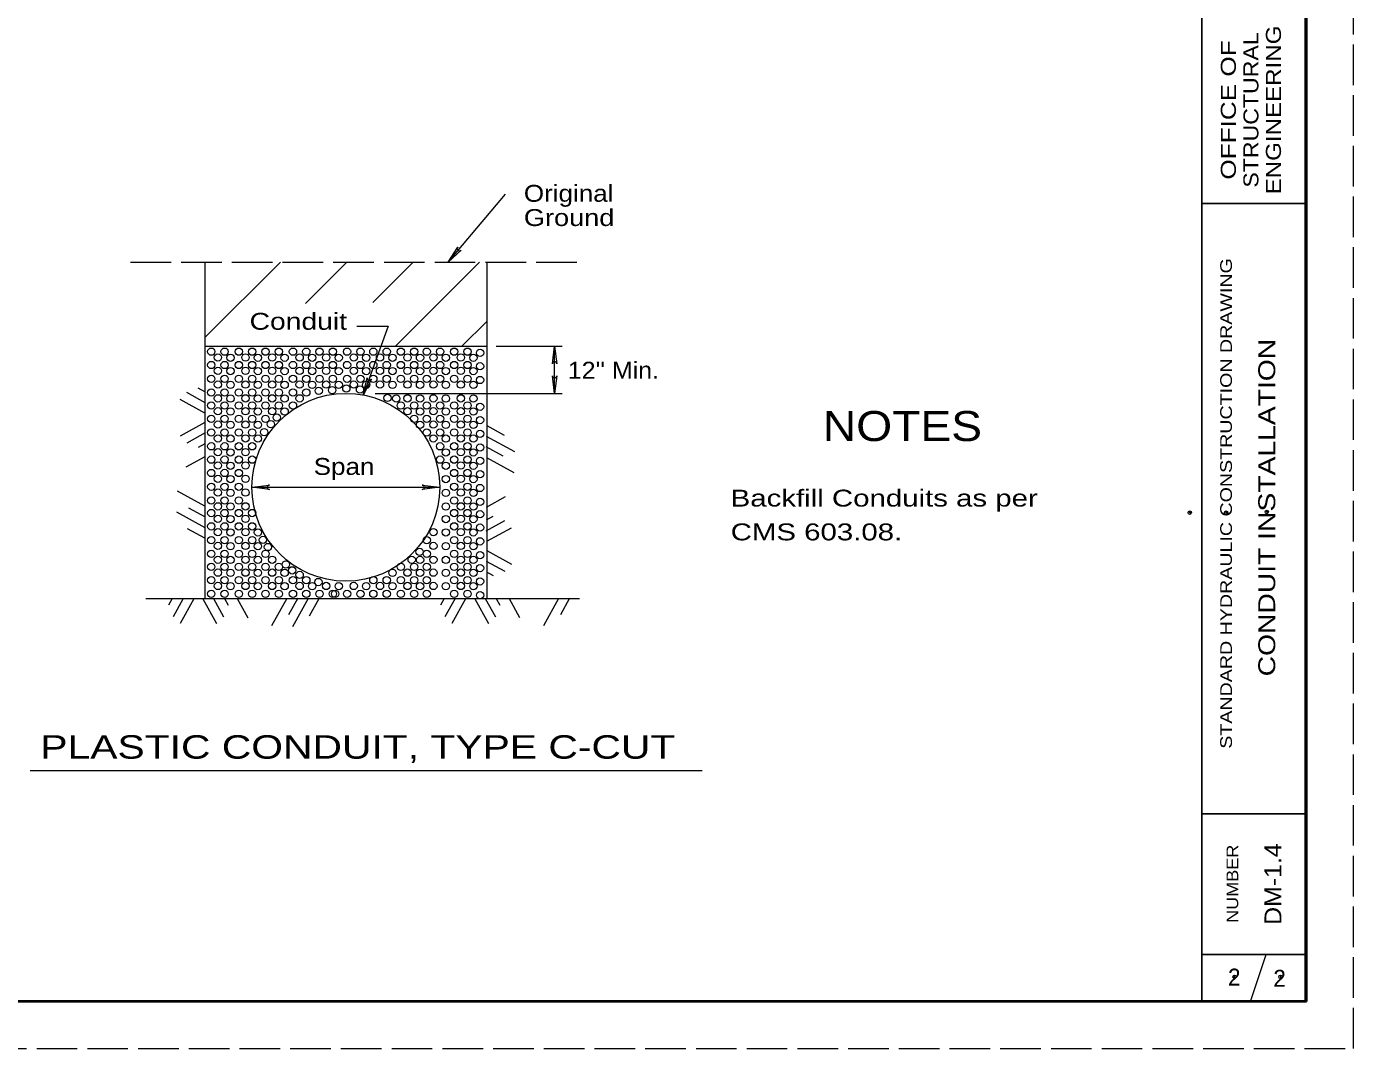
# Model space of a CAD drawing. Extents: x 750.7 to 784.7, y 834.8 to 878.8.
# Drawn here: x 770.52 to 784.65, y 834.78 to 845.67 of the extents above; entities that cross this region are included whole.
import ezdxf
from ezdxf.enums import TextEntityAlignment as Align

# ---------------------------------------------------------------- set-up
doc = ezdxf.new("R2010")
doc.units = 0
doc.header["$LTSCALE"] = 0.072
doc.header["$PDMODE"] = 32
doc.header["$PDSIZE"] = 0.036
doc.linetypes.add('LONG_DASHED', pattern=[7.5, 6, -1.5])
doc.layers.add('1', color=7, linetype='Continuous', lineweight=13)
doc.layers.add('47', color=7, linetype='Continuous', lineweight=13)

msp = doc.modelspace()

# ---------------------------------------------------------------- linework, layer by layer
at = {"layer": '1', "lineweight": 25}
for p, q in [((783.03717, 835.28433), (783.03717, 856.28433)), ((784.13717, 856.28433), (784.13717, 835.28433)), ((784.13717, 843.78433), (783.03717, 843.78433)), ((784.13717, 837.28433), (783.03717, 837.28433)), ((784.13717, 835.78433), (783.03717, 835.78433)), ((784.15083, 835.28433), (752.65083, 835.28433))]:
    msp.add_line(p, q, dxfattribs=at)
at = {"layer": '1', "lineweight": 40}
msp.add_line((784.147, 856.28433), (784.147, 835.28433), dxfattribs=at)
at = {"layer": '1'}
for p, q in [((775.01125, 843.15875), (775.62233, 843.88067)), ((772.42208, 843.15875), (772.42208, 839.5755)), ((772.42208, 842.35508), (773.22567, 843.15875)), ((773.4925, 842.71842), (773.93275, 843.15875)), ((774.21, 842.72883), (774.63983, 843.15875)), ((774.45017, 842.26192), (775.34692, 843.15875)), ((775.42208, 843.15875), (775.42208, 839.5755)), ((775.15717, 842.26192), (775.42208, 842.52683)), ((772.42208, 842.26192), (775.42208, 842.26192)), ((775.52308, 842.26192), (776.22442, 842.26192)), ((776.1445, 841.76058), (776.1445, 842.26192)), ((772.4235, 841.66092), (772.228, 841.76875)), ((772.42208, 841.7775), (772.35075, 841.81683)), ((774.236, 841.76058), (776.22442, 841.76058)), ((772.41958, 841.54883), (772.157, 841.69375)), ((772.41958, 841.45092), (772.157, 841.306)), ((772.4235, 841.33883), (772.228, 841.231)), ((775.42208, 841.41875), (775.6065, 841.317)), ((772.42208, 841.22225), (772.35075, 841.18292)), ((775.41425, 841.19467), (775.59267, 841.09625)), ((775.41817, 841.30667), (775.71933, 841.1405)), ((772.42258, 841.08592), (772.2185, 840.97333)), ((775.41958, 841.0775), (775.71058, 840.91692)), ((772.42208, 840.55875), (772.13108, 840.71933)), ((772.92208, 840.76083), (774.92208, 840.76083)), ((775.41908, 840.55033), (775.62317, 840.66292)), ((772.4235, 840.32958), (772.12233, 840.49575)), ((772.42742, 840.44158), (772.249, 840.54)), ((775.41817, 840.29742), (775.61367, 840.40525)), ((775.41958, 840.414), (775.49092, 840.45333)), ((772.41958, 840.2175), (772.23517, 840.31925)), ((775.42208, 840.18533), (775.68467, 840.33025)), ((775.42208, 840.08742), (775.68467, 839.9425)), ((775.41817, 839.97533), (775.61367, 839.8675)), ((775.41958, 839.85875), (775.49092, 839.81942)), ((771.79442, 839.5755), (776.40983, 839.5755)), ((772.0745, 839.5755), (772.03517, 839.50417)), ((772.19108, 839.57692), (772.08325, 839.38142)), ((772.30317, 839.573), (772.15825, 839.31042)), ((772.40108, 839.573), (772.546, 839.31042)), ((772.51317, 839.57692), (772.621, 839.38142)), ((772.62975, 839.5755), (772.66908, 839.50417)), ((772.76608, 839.576), (772.87867, 839.37192)), ((773.29325, 839.5755), (773.13267, 839.2845)), ((773.41042, 839.58083), (773.312, 839.40242)), ((773.52242, 839.57692), (773.35625, 839.27575)), ((773.6345, 839.573), (773.53275, 839.38858)), ((774.96892, 839.57617), (774.92958, 839.50483)), ((775.0855, 839.57758), (774.97767, 839.38208)), ((775.19758, 839.57367), (775.05267, 839.31108)), ((775.2955, 839.57367), (775.44042, 839.31108)), ((775.40758, 839.57758), (775.51542, 839.38208)), ((775.52417, 839.57617), (775.5635, 839.50483)), ((775.6605, 839.57667), (775.77308, 839.37258)), ((776.18767, 839.57617), (776.02708, 839.28517)), ((776.30483, 839.5815), (776.20642, 839.40308)), ((770.56125, 837.74617), (777.71625, 837.74617)), ((783.55383, 835.28433), (783.7205, 835.78433))]:
    msp.add_line(p, q, dxfattribs=at)
at = {"layer": '1', "linetype": 'LONG_DASHED'}
msp.add_line((771.62908, 843.15875), (776.42258, 843.15875), dxfattribs=at)
msp.add_lwpolyline([(750.65083, 834.78433), (784.65083, 834.78433), (784.65083, 856.78433), (750.65083, 856.78433)], close=True, dxfattribs=at)
at = {"layer": '1', "lineweight": 40}
for points in [[(784.15083, 835.28433), (752.65083, 835.28433), (752.65083, 856.28433), (784.15083, 856.28433)], [(784.15083, 835.28433), (752.65083, 835.28433), (752.65083, 856.28433)]]:
    msp.add_lwpolyline(points, dxfattribs=at)
at = {"layer": '1'}
msp.add_lwpolyline([(774.0385, 842.47633), (774.37317, 842.47633), (774.10817, 841.74333)], dxfattribs=at)
for centre, radius in [((772.48963, 842.20494), 0.03892), ((772.56066, 842.14281), 0.03892), ((772.63166, 842.20497), 0.03892), ((772.69383, 842.14047), 0.03892), ((772.78255, 842.20494), 0.03892), ((772.85358, 842.14281), 0.03892), ((772.92458, 842.20497), 0.03892), ((772.98674, 842.14047), 0.03892), ((773.06663, 842.20494), 0.03892), ((773.13766, 842.14281), 0.03892), ((773.20866, 842.20497), 0.03892), ((773.27083, 842.14047), 0.03892), ((773.35955, 842.20494), 0.03892), ((773.43058, 842.14281), 0.03892), ((773.50158, 842.20497), 0.03892), ((773.56374, 842.14047), 0.03892), ((773.64263, 842.20494), 0.03892), ((773.71366, 842.14281), 0.03892), ((773.78466, 842.20497), 0.03892), ((773.84683, 842.14047), 0.03892), ((773.93555, 842.20494), 0.03892), ((774.00658, 842.14281), 0.03892), ((774.07758, 842.20497), 0.03892), ((774.13974, 842.14047), 0.03892), ((774.21521, 842.20494), 0.03892), ((774.28624, 842.14281), 0.03892), ((774.35724, 842.20497), 0.03892), ((774.41941, 842.14047), 0.03892), ((774.50813, 842.20494), 0.03892), ((774.57916, 842.14281), 0.03892), ((774.65016, 842.20497), 0.03892), ((774.71233, 842.14047), 0.03892), ((774.78338, 842.20494), 0.03892), ((774.85441, 842.14281), 0.03892), ((774.92541, 842.20497), 0.03892), ((774.98758, 842.14047), 0.03892), ((775.0763, 842.20494), 0.03892), ((775.14733, 842.14281), 0.03892), ((775.21833, 842.20497), 0.03892), ((775.28049, 842.14047), 0.03892), ((775.35149, 842.19164), 0.03892), ((772.48963, 842.06286), 0.03892), ((772.56066, 842.00072), 0.03892), ((772.63166, 842.06289), 0.03892), ((772.69383, 841.99839), 0.03892), ((772.78255, 842.06286), 0.03892), ((772.85358, 842.00072), 0.03892), ((772.92458, 842.06289), 0.03892), ((772.98674, 841.99839), 0.03892), ((773.06663, 842.06286), 0.03892), ((773.13766, 842.00072), 0.03892), ((773.20866, 842.06289), 0.03892), ((773.27083, 841.99839), 0.03892), ((773.35955, 842.06286), 0.03892), ((773.43058, 842.00072), 0.03892), ((773.50158, 842.06289), 0.03892), ((773.56374, 841.99839), 0.03892), ((773.64263, 842.06286), 0.03892), ((773.71366, 842.00072), 0.03892), ((773.78466, 842.06289), 0.03892), ((773.84683, 841.99839), 0.03892), ((773.93555, 842.06286), 0.03892), ((774.00658, 842.00072), 0.03892), ((774.07758, 842.06289), 0.03892), ((774.13974, 841.99839), 0.03892), ((774.21521, 842.06286), 0.03892), ((774.28624, 842.00072), 0.03892), ((774.35724, 842.06289), 0.03892), ((774.41941, 841.99839), 0.03892), ((774.50813, 842.06286), 0.03892), ((774.57916, 842.00072), 0.03892), ((774.65016, 842.06289), 0.03892), ((774.71233, 841.99839), 0.03892), ((774.78338, 842.06286), 0.03892), ((774.85441, 842.00072), 0.03892), ((774.92541, 842.06289), 0.03892), ((774.98758, 841.99839), 0.03892), ((775.0763, 842.06286), 0.03892), ((775.14733, 842.00072), 0.03892), ((775.21833, 842.06289), 0.03892), ((775.28049, 841.99839), 0.03892), ((775.35149, 842.04956), 0.03892), ((772.48963, 841.91636), 0.03892), ((772.63166, 841.91639), 0.03892), ((772.78255, 841.91636), 0.03892), ((772.92458, 841.91639), 0.03892), ((773.06663, 841.91636), 0.03892), ((773.20866, 841.91639), 0.03892), ((773.35955, 841.91636), 0.03892), ((773.50158, 841.91639), 0.03892), ((773.64263, 841.91636), 0.03892), ((773.78466, 841.91639), 0.03892), ((773.93555, 841.91636), 0.03892), ((774.07758, 841.91639), 0.03892), ((774.21521, 841.91636), 0.03892), ((774.35724, 841.91639), 0.03892), ((774.50813, 841.91636), 0.03892), ((774.65016, 841.91639), 0.03892), ((774.78338, 841.91636), 0.03892), ((774.92541, 841.91639), 0.03892), ((775.0763, 841.91636), 0.03892), ((775.21833, 841.91639), 0.03892), ((775.35149, 841.90306), 0.03892), ((772.48963, 841.76978), 0.03892), ((772.56066, 841.85422), 0.03892), ((772.63166, 841.76981), 0.03892), ((772.69383, 841.85189), 0.03892), ((772.78255, 841.76978), 0.03892), ((772.85358, 841.85422), 0.03892), ((772.92458, 841.76981), 0.03892), ((773.92208, 840.76083), 1), ((772.98674, 841.85189), 0.03892), ((773.06663, 841.76978), 0.03892), ((773.13766, 841.85422), 0.03892), ((773.20866, 841.76981), 0.03892), ((773.27083, 841.85189), 0.03892), ((773.35955, 841.76978), 0.03892), ((773.43058, 841.85422), 0.03892), ((773.50158, 841.76981), 0.03892), ((773.56374, 841.85189), 0.03892), ((773.63373, 841.78758), 0.03892), ((773.71366, 841.85422), 0.03892), ((773.77683, 841.79412), 0.03892), ((773.84683, 841.85189), 0.03892), ((773.92767, 841.81187), 0.03892), ((774.00658, 841.85422), 0.03892), ((774.07315, 841.80086), 0.03892), ((774.13974, 841.85189), 0.03892), ((774.28624, 841.85422), 0.03892), ((774.41941, 841.85189), 0.03892), ((774.57916, 841.85422), 0.03892), ((774.71233, 841.85189), 0.03892), ((774.85441, 841.85422), 0.03892), ((774.98758, 841.85189), 0.03892), ((775.14733, 841.85422), 0.03892), ((775.28049, 841.85189), 0.03892), ((772.48963, 841.63211), 0.03892), ((772.56066, 841.70764), 0.03892), ((772.63166, 841.63214), 0.03892), ((772.69383, 841.70531), 0.03892), ((772.78255, 841.63211), 0.03892), ((772.85358, 841.70764), 0.03892), ((772.92458, 841.63214), 0.03892), ((772.98674, 841.70531), 0.03892), ((773.06663, 841.63211), 0.03892), ((773.13766, 841.70764), 0.03892), ((773.20866, 841.63214), 0.03892), ((773.27083, 841.70531), 0.03892), ((773.35955, 841.63211), 0.03892), ((773.43058, 841.70764), 0.03892), ((774.36614, 841.71203), 0.03892), ((774.45934, 841.70528), 0.03892), ((774.50813, 841.63211), 0.03892), ((774.57916, 841.70764), 0.03892), ((774.65016, 841.63214), 0.03892), ((774.71233, 841.70531), 0.03892), ((774.78338, 841.63211), 0.03892), ((774.85441, 841.70764), 0.03892), ((774.92541, 841.63214), 0.03892), ((774.98758, 841.70531), 0.03892), ((775.0763, 841.63211), 0.03892), ((775.14733, 841.70764), 0.03892), ((775.21833, 841.63214), 0.03892), ((775.28049, 841.70531), 0.03892), ((775.35149, 841.61881), 0.03892), ((772.48963, 841.49003), 0.03892), ((772.56066, 841.56997), 0.03892), ((772.63166, 841.49006), 0.03892), ((772.69383, 841.56764), 0.03892), ((772.78255, 841.49003), 0.03892), ((772.85358, 841.56997), 0.03892), ((772.92458, 841.49006), 0.03892), ((772.98674, 841.56764), 0.03892), ((773.06663, 841.49003), 0.03892), ((773.12433, 841.43236), 0.03892), ((773.13766, 841.56997), 0.03892), ((773.18642, 841.50338), 0.03892), ((773.27083, 841.56764), 0.03892), ((774.57916, 841.56997), 0.03892), ((774.65016, 841.49006), 0.03892), ((774.71233, 841.56764), 0.03892), ((774.78338, 841.49003), 0.03892), ((774.85441, 841.56997), 0.03892), ((774.92541, 841.49006), 0.03892), ((774.98758, 841.56764), 0.03892), ((775.0763, 841.49003), 0.03892), ((775.14733, 841.56997), 0.03892), ((775.21833, 841.49006), 0.03892), ((775.28049, 841.56764), 0.03892), ((775.35149, 841.47672), 0.03892), ((772.48963, 841.34353), 0.03892), ((772.56066, 841.42789), 0.03892), ((772.63166, 841.34356), 0.03892), ((772.69383, 841.42556), 0.03892), ((772.78255, 841.34353), 0.03892), ((772.85358, 841.42789), 0.03892), ((772.92458, 841.34356), 0.03892), ((772.98674, 841.42556), 0.03892), ((773.05334, 841.34794), 0.03892), ((774.71233, 841.42556), 0.03892), ((774.78338, 841.34353), 0.03892), ((774.85441, 841.42789), 0.03892), ((774.92541, 841.34356), 0.03892), ((774.98758, 841.42556), 0.03892), ((775.0763, 841.34353), 0.03892), ((775.14733, 841.42789), 0.03892), ((775.21833, 841.34356), 0.03892), ((775.28049, 841.42556), 0.03892), ((775.35149, 841.33022), 0.03892), ((772.48963, 841.19694), 0.03892), ((772.56066, 841.28139), 0.03892), ((772.63166, 841.19697), 0.03892), ((772.69383, 841.27906), 0.03892), ((772.78255, 841.19694), 0.03892), ((772.85358, 841.28139), 0.03892), ((772.92458, 841.19697), 0.03892), ((772.98674, 841.27906), 0.03892), ((774.85441, 841.28139), 0.03892), ((774.92541, 841.19697), 0.03892), ((774.98758, 841.27906), 0.03892), ((775.0763, 841.19694), 0.03892), ((775.14733, 841.28139), 0.03892), ((775.21833, 841.19697), 0.03892), ((775.28049, 841.27906), 0.03892), ((775.35149, 841.18364), 0.03892), ((772.48963, 841.05494), 0.03892), ((772.56066, 841.13481), 0.03892), ((772.63166, 841.05497), 0.03892), ((772.69383, 841.13247), 0.03892), ((772.78255, 841.05494), 0.03892), ((772.85358, 841.13481), 0.03892), ((772.92458, 841.05497), 0.03892), ((774.92541, 841.05497), 0.03892), ((774.98758, 841.13247), 0.03892), ((775.0763, 841.05494), 0.03892), ((775.14733, 841.13481), 0.03892), ((775.21833, 841.05497), 0.03892), ((775.28049, 841.13247), 0.03892), ((775.35149, 841.04164), 0.03892), ((772.48963, 840.91286), 0.03892), ((772.56066, 840.99281), 0.03892), ((772.63166, 840.91289), 0.03892), ((772.69383, 840.99047), 0.03892), ((772.78255, 840.91286), 0.03892), ((772.85358, 840.99281), 0.03892), ((774.98758, 840.99047), 0.03892), ((775.0763, 840.91286), 0.03892), ((775.14733, 840.99281), 0.03892), ((775.21833, 840.91289), 0.03892), ((775.28049, 840.99047), 0.03892), ((775.35149, 840.89956), 0.03892), ((772.48963, 840.76636), 0.03892), ((772.56066, 840.85072), 0.03892), ((772.63166, 840.76639), 0.03892), ((772.69383, 840.84839), 0.03892), ((772.78255, 840.76636), 0.03892), ((772.85358, 840.85072), 0.03892), ((774.98758, 840.84839), 0.03892), ((775.0763, 840.76636), 0.03892), ((775.14733, 840.85072), 0.03892), ((775.21833, 840.76639), 0.03892), ((775.28049, 840.84839), 0.03892), ((775.35149, 840.75306), 0.03892), ((772.48963, 840.61978), 0.03892), ((772.56066, 840.70422), 0.03892), ((772.63166, 840.61981), 0.03892), ((772.69383, 840.70189), 0.03892), ((772.78255, 840.61978), 0.03892), ((772.85358, 840.70422), 0.03892), ((774.98758, 840.70189), 0.03892), ((775.0763, 840.61978), 0.03892), ((775.14733, 840.70422), 0.03892), ((775.21833, 840.61981), 0.03892), ((775.28049, 840.70189), 0.03892), ((775.35149, 840.60647), 0.03892), ((772.48963, 840.48661), 0.03892), ((772.56066, 840.55764), 0.03892), ((772.63166, 840.48664), 0.03892), ((772.69383, 840.55531), 0.03892), ((772.78255, 840.48661), 0.03892), ((772.85358, 840.55764), 0.03892), ((772.92458, 840.48664), 0.03892), ((774.98758, 840.55531), 0.03892), ((775.0763, 840.48661), 0.03892), ((775.14733, 840.55764), 0.03892), ((775.21833, 840.48664), 0.03892), ((775.28049, 840.55531), 0.03892), ((775.35149, 840.47331), 0.03892), ((772.48963, 840.34453), 0.03892), ((772.56066, 840.42447), 0.03892), ((772.63166, 840.34456), 0.03892), ((772.69383, 840.42214), 0.03892), ((772.78255, 840.34453), 0.03892), ((772.85358, 840.42447), 0.03892), ((772.92458, 840.34456), 0.03892), ((774.98758, 840.42214), 0.03892), ((775.0763, 840.34453), 0.03892), ((775.14733, 840.42447), 0.03892), ((775.21833, 840.34456), 0.03892), ((775.28049, 840.42214), 0.03892), ((775.35149, 840.33122), 0.03892), ((772.48963, 840.19803), 0.03892), ((772.56066, 840.28239), 0.03892), ((772.63166, 840.19806), 0.03892), ((772.69383, 840.28006), 0.03892), ((772.78255, 840.19803), 0.03892), ((772.85358, 840.28239), 0.03892), ((772.92458, 840.19806), 0.03892), ((772.98674, 840.28006), 0.03892), ((773.04, 840.20012), 0.03892), ((774.78338, 840.19803), 0.03892), ((774.85441, 840.28239), 0.03892), ((774.98758, 840.28006), 0.03892), ((775.0763, 840.19803), 0.03892), ((775.14733, 840.28239), 0.03892), ((775.21833, 840.19806), 0.03892), ((775.28049, 840.28006), 0.03892), ((775.35149, 840.18472), 0.03892), ((772.48963, 840.05144), 0.03892), ((772.56066, 840.13589), 0.03892), ((772.63166, 840.05147), 0.03892), ((772.69383, 840.13356), 0.03892), ((772.78255, 840.05144), 0.03892), ((772.85358, 840.13589), 0.03892), ((772.92458, 840.05147), 0.03892), ((772.98674, 840.13356), 0.03892), ((773.06663, 840.05144), 0.03892), ((773.09325, 840.12462), 0.03892), ((774.70785, 840.07367), 0.03892), ((774.78338, 840.05144), 0.03892), ((774.85441, 840.13589), 0.03892), ((774.98758, 840.13356), 0.03892), ((775.0763, 840.05144), 0.03892), ((775.14733, 840.13589), 0.03892), ((775.21833, 840.05147), 0.03892), ((775.28049, 840.13356), 0.03892), ((775.35149, 840.03814), 0.03892), ((772.48963, 839.91378), 0.03892), ((772.56066, 839.98931), 0.03892), ((772.63166, 839.91381), 0.03892), ((772.69383, 839.98697), 0.03892), ((772.78255, 839.91378), 0.03892), ((772.85358, 839.98931), 0.03892), ((772.92458, 839.91381), 0.03892), ((772.98674, 839.98697), 0.03892), ((773.06663, 839.91378), 0.03892), ((773.13766, 839.98931), 0.03892), ((773.20866, 839.91381), 0.03892), ((773.28408, 839.93821), 0.03892), ((774.50813, 839.91378), 0.03892), ((774.62351, 839.98926), 0.03892), ((774.65016, 839.91381), 0.03892), ((774.71233, 839.98697), 0.03892), ((774.78338, 839.91378), 0.03892), ((774.85441, 839.98931), 0.03892), ((774.98758, 839.98697), 0.03892), ((775.0763, 839.91378), 0.03892), ((775.14733, 839.98931), 0.03892), ((775.21833, 839.91381), 0.03892), ((775.28049, 839.98697), 0.03892), ((775.35149, 839.90047), 0.03892), ((772.48963, 839.77169), 0.03892), ((772.56066, 839.85164), 0.03892), ((772.63166, 839.77172), 0.03892), ((772.69383, 839.84931), 0.03892), ((772.78255, 839.77169), 0.03892), ((772.85358, 839.85164), 0.03892), ((772.92458, 839.77172), 0.03892), ((772.98674, 839.84931), 0.03892), ((773.06663, 839.77169), 0.03892), ((773.13766, 839.85164), 0.03892), ((773.20866, 839.77172), 0.03892), ((773.27083, 839.84931), 0.03892), ((773.35067, 839.87604), 0.03892), ((773.35955, 839.77169), 0.03892), ((773.43058, 839.82712), 0.03892), ((773.50158, 839.77172), 0.03892), ((773.63033, 839.75171), 0.03892), ((774.21521, 839.77169), 0.03892), ((774.35724, 839.77172), 0.03892), ((774.41941, 839.84931), 0.03892), ((774.50813, 839.77169), 0.03892), ((774.57916, 839.85164), 0.03892), ((774.65016, 839.77172), 0.03892), ((774.71233, 839.84931), 0.03892), ((774.78338, 839.77169), 0.03892), ((774.85441, 839.85164), 0.03892), ((774.98758, 839.84931), 0.03892), ((775.0763, 839.77169), 0.03892), ((775.14733, 839.85164), 0.03892), ((775.21833, 839.77172), 0.03892), ((775.28049, 839.84931), 0.03892), ((775.35149, 839.75839), 0.03892), ((772.48963, 839.62519), 0.03892), ((772.56066, 839.70956), 0.03892), ((772.63166, 839.62522), 0.03892), ((772.69383, 839.70722), 0.03892), ((772.78255, 839.62519), 0.03892), ((772.85358, 839.70956), 0.03892), ((772.92458, 839.62522), 0.03892), ((772.98674, 839.70722), 0.03892), ((773.06663, 839.62519), 0.03892), ((773.13766, 839.70956), 0.03892), ((773.20866, 839.62522), 0.03892), ((773.27083, 839.70722), 0.03892), ((773.35955, 839.62519), 0.03892), ((773.43058, 839.70956), 0.03892), ((773.50158, 839.62522), 0.03892), ((773.56374, 839.70722), 0.03892), ((773.64263, 839.62519), 0.03892), ((773.71366, 839.70956), 0.03892), ((773.78466, 839.62522), 0.03892), ((773.80813, 839.62519), 0.03892), ((773.84683, 839.70722), 0.03892), ((773.93555, 839.62519), 0.03892), ((774.00658, 839.70956), 0.03892), ((774.07758, 839.62522), 0.03892), ((774.13974, 839.70722), 0.03892), ((774.21521, 839.62519), 0.03892), ((774.28624, 839.70956), 0.03892), ((774.35724, 839.62522), 0.03892), ((774.41941, 839.70722), 0.03892), ((774.50813, 839.62519), 0.03892), ((774.57916, 839.70956), 0.03892), ((774.65016, 839.62522), 0.03892), ((774.71233, 839.70722), 0.03892), ((774.78338, 839.62519), 0.03892), ((774.85441, 839.70956), 0.03892), ((774.98758, 839.70722), 0.03892), ((775.0763, 839.62519), 0.03892), ((775.14733, 839.70956), 0.03892), ((775.21833, 839.62522), 0.03892), ((775.28049, 839.70722), 0.03892), ((775.35149, 839.61189), 0.03892)]:
    msp.add_circle(centre, radius, dxfattribs=at)
for p in [(782.90825, 840.49033), (783.29458, 840.49033), (783.72742, 840.49767), (783.38525, 835.54808), (783.87367, 835.54708)]:
    msp.add_point(p, dxfattribs=at)
at = {"layer": '47'}
for points in [[(775.15025, 843.28675), (775.01125, 843.15875), (775.1145, 843.317)], [(776.12108, 842.07442), (776.1445, 842.26192), (776.16792, 842.07442)], [(774.19392, 841.91167), (774.10817, 841.74333), (774.14992, 841.92767)], [(776.16792, 841.94808), (776.1445, 841.76058), (776.12108, 841.94808)], [(773.10958, 840.73742), (772.92208, 840.76083), (773.10958, 840.78425)], [(774.73458, 840.78425), (774.92208, 840.76083), (774.73458, 840.73742)]]:
    msp.add_lwpolyline(points, dxfattribs=at)
for centre, start, end in [((775.13239, 843.30187), 139.75297, 319.75297), ((776.14451, 842.07441), 0, 180), ((774.17191, 841.91967), 160.12536, 340.12536), ((776.14449, 841.94809), 180, 0), ((773.10959, 840.76084), 90, 270), ((774.73458, 840.76083), 270, 90)]:
    msp.add_arc(centre, 0.02342, start, end, dxfattribs=at)

# ---------------------------------------------------------------- texts
at = {"layer": '1'}
for s, height, width, p in [('STRUCTURAL', 0.16, 1.15, (783.63892, 844.77871)), ('ENGINEERING', 0.16, 1.2, (783.87892, 844.77879)), ('OFFICE OF', 0.16, 1.3, (783.39892, 844.77871)), ('STANDARD HYDRAULIC CONSTRUCTION DRAWING', 0.125, 1.25, (783.35708, 840.58829)), ('CONDUIT INSTALLATION', 0.18, 1.25, (783.81758, 840.54442)), ('DM-1.4', 0.18, 1.1, (783.88325, 836.53458)), ('NUMBER', 0.125, 1.15, (783.42417, 836.53833))]:
    msp.add_text(s, height=height, rotation=90, dxfattribs=dict(at, width=width)).set_placement(p, align=Align.CENTER)
for s, height, width, p in [('Original', 0.18, 1.15, (775.818, 843.801)), ('Ground', 0.18, 1.2, (775.818, 843.543)), ('Conduit', 0.18, 1.25, (772.8975, 842.43825)), ("12'' Min.", 0.18, 1.1, (776.28658, 841.91725)), ('NOTES', 0.32, 1.15, (779.001, 841.25275)), ('Span', 0.18, 1.15, (773.58033, 840.89242)), ('Backfill Conduits as per ', 0.18, 1.3, (778.01992, 840.55525)), ('CMS 603.08.', 0.18, 1.3, (778.01992, 840.19525)), ('PLASTIC CONDUIT, TYPE C-CUT', 0.25, 1.3, (770.66967, 837.87025))]:
    msp.add_text(s, height=height, dxfattribs=dict(at, width=width)).set_placement(p)
for p in [(783.38162, 835.45433), (783.86446, 835.44175)]:
    msp.add_text('2', height=0.18, dxfattribs=at).set_placement(p, align=Align.CENTER)

doc.saveas('drawing.dxf')
